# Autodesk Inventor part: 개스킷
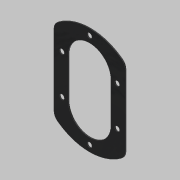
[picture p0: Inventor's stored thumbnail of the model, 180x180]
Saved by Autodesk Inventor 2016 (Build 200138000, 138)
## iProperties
Created: 2019-03
Part Number: 개스킷
Material: 고무
Document SubType Name: Modeling
Designer: mduedu
Density: 1 g/cm^3
Appearance: 고무 - 검은색 - 버전 1.1
Author: mduedu
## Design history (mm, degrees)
sketch "스케치1"
  geometry: L1 (-44.721, -40)-(44.721, -40); L2 (44.721, 40)-(-44.721, 40); A1 r 60 centre (0, 0) between (44.721, -40) and (44.721, 40); A2 r 60 centre (0, 0) between (-44.721, 40) and (-44.721, -40); 5 further points
  constraints: 6 point on circle, 4 end point, 2 centre point, 2 coincident, 2 horizontal alignment, 2 midpoint, 2 vertical alignment, 1 horizontal, 1 parallel
  dimensions: "d0" = 60 radius of A1; "d2" = 80 distance between parallel lines of L2 L1
extrude "돌출1" new body sketch "스케치1" distance "d3" = 1; taper "d4" = 0 deg
fillet "모깎기1" dims "d5" = 10
sketch "스케치2" dims "d6" = 48
  geometry: L1 (-24, -22)-(24, -22); L2 (24, -22)-(24, 22); L3 (24, 22)-(-24, 22); L4 (-24, 22)-(-24, -22); L5 (-24, -22)-(24, 22); L6 (24, -22)-(-24, 22); 3 further points
  constraints: 12 end point, 4 midpoint, 2 horizontal alignment, 2 parallel, 1 horizontal, 1 perpendicular, 4 other
  dimensions: "d8" = 22 distance from line of L3 point (0, 0)
extrude "돌출2" cut sketch "스케치2" stored distance "d9" = 1; taper "d10" = 0 deg
sketch "스케치3" dims "d0" = 60, "d2" = 80
  geometry: L1 (31, -22)-(31, 22); L2 (-31, 22)-(-31, -22); L3 (-31, -22)-(31, 22); L4 (31, -22)-(-31, 22); A1 r 31 centre (0, 22) between (31, 22) and (-31, 22); A2 r 31 centre (0, -22) between (-31, -22) and (31, -22); 8 further points
  constraints: 8 end point, 6 point on circle, 4 coincident, 4 midpoint, 3 tangent, 2 centre point, 2 vertical alignment, 1 parallel
  dimensions: "d11" = 31 radius of A1; "d13" = 44 distance of A2.centre A1.centre
hole "구멍1" sketch "스케치3" at (-31, 22), (-31, -22), (31, -22), (31, 22), (0, -53), (0, 53) diameter "d14" = 5.5; stored, may be unused: countersink angle "d18" = 90 deg, drill point angle "d20" = 118 deg; dims "d15" = 6, "d16" = 4, "d17" = 2, "d19" = 8
node "솔리드1"
